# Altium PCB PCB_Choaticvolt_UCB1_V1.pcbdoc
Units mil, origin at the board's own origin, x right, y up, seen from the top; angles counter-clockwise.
Board outline 5539.37 x 2906.58 mil, 2 copper layers (Top Layer, Bottom Layer); 21 components, 11 nets, 90 pads, 17 vias.
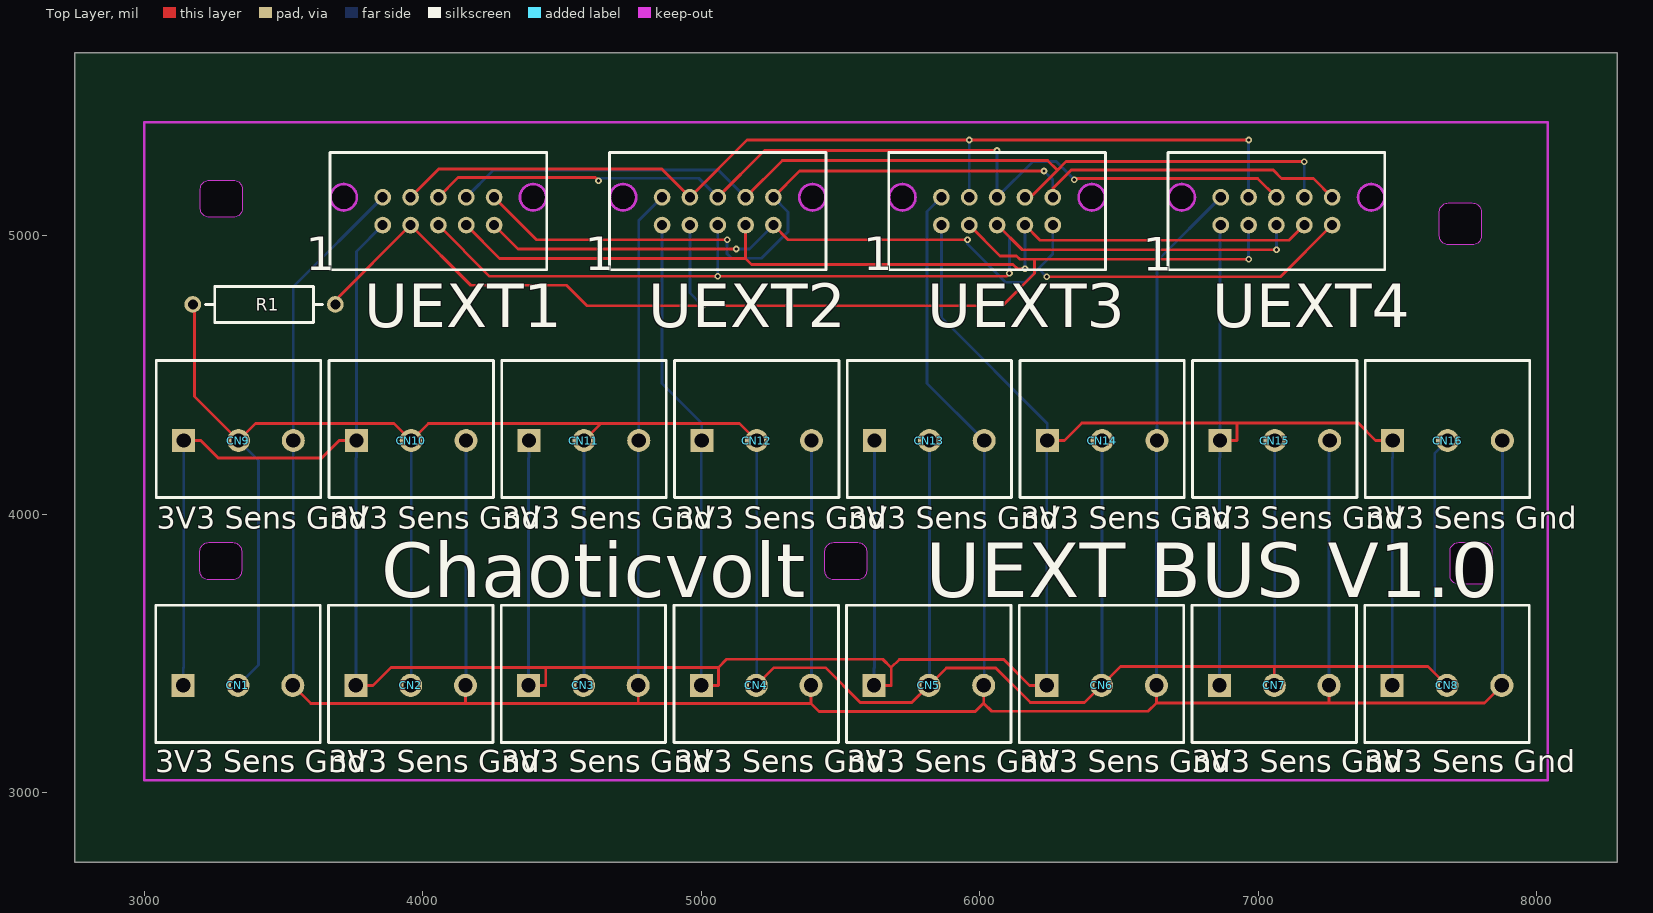
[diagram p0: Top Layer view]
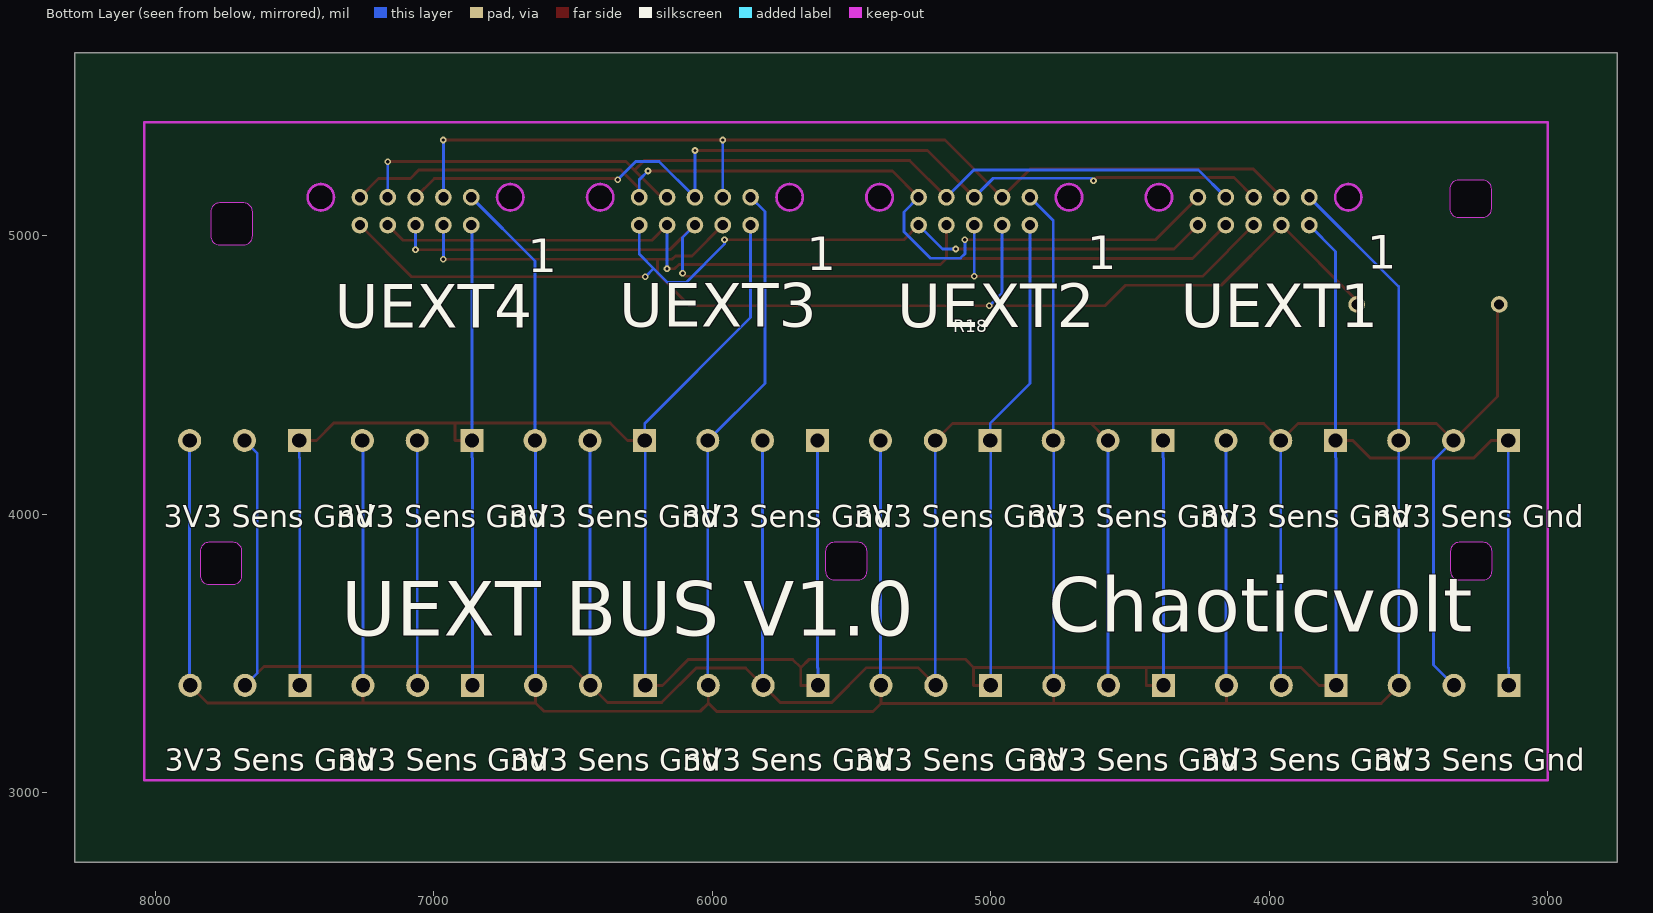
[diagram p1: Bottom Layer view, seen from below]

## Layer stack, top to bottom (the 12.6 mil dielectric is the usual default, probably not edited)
Top Layer: signal copper (thickness not stored)
Dielectric: dielectric 12.6, FR-4, Dk 4.8
Bottom Layer: signal copper (thickness not stored)

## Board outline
8289.37,2750 2750,2750 2750,5656.58 8289.37,5656.58
cut-out: 7682.22,5116.99 7769.23,5116.99 cw(c7769.23,5085.49) 7800.72,5085.49 7800.72,4998.49 cw(c7769.23,4998.49) 7769.23,4966.99 7682.22,4966.99 cw(c7682.22,4998.49) 7650.72,4998.49 7650.72,5085.49 cw(c7682.22,5085.49)
cut-out: 3233.09,5198.99 3319.7,5198.99 cw(c3319.7,5167.49) 3351.2,5167.49 3351.2,5096.63 cw(c3319.7,5096.63) 3319.7,5065.13 3233.09,5065.13 cw(c3233.09,5096.63) 3201.59,5096.63 3201.59,5167.49 cw(c3233.09,5167.49)
cut-out: 3231.09,3897.88 3317.7,3897.88 cw(c3317.7,3866.38) 3349.2,3866.38 3349.2,3795.52 cw(c3317.7,3795.52) 3317.7,3764.02 3231.09,3764.02 cw(c3231.09,3795.52) 3199.59,3795.52 3199.59,3866.38 cw(c3231.09,3866.38)
cut-out: 7720.22,3897.88 7807.23,3897.88 cw(c7807.23,3866.38) 7838.72,3866.38 7838.72,3779.38 cw(c7807.23,3779.38) 7807.23,3747.88 7720.22,3747.88 cw(c7720.22,3779.38) 7688.72,3779.38 7688.72,3866.38 cw(c7720.22,3866.38)
cut-out: 5475.52,3897.88 5562.13,3897.88 cw(c5562.13,3866.38) 5593.63,3866.38 5593.63,3795.52 cw(c5562.13,3795.52) 5562.13,3764.02 5475.52,3764.02 cw(c5475.52,3795.52) 5444.02,3795.52 5444.02,3866.38 cw(c5475.52,3866.38)

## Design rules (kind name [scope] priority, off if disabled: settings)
Clearance copperThickness1oz [All] p1: gap=7 ignorepadtopadclearanceinfootprint=FALSE except(4: Track-Track; 6: Track-SMDPad SMDPad-SMDPad Track-THPad SMDPad-THPad THPad-THPad Track-Via SMDPad-Via THPad-Via Via-Via SMDPad-Fill THPad-Fill Via-Fill Fill-Fill Track-Region SMDPad-Region THPad-Region Via-Region Region-Region Track-Poly SMDPad-Poly THPad-Poly Via-Poly Fill-Poly Region-Poly Poly-Poly Track-Text SMDPad-Text THPad-Text Via-Text Fill-Text Region-Text Poly-Text Text-Text; 6.9: Track-Hole SMDPad-Hole THPad-Hole Via-Hole Fill-Hole Region-Hole Poly-Hole Text-Hole Sheet-Hole; 11.8: Track-Fill Fill-Region Track-Sheet SMDPad-Sheet THPad-Sheet Via-Sheet Fill-Sheet Region-Sheet Poly-Sheet Text-Sheet)
Clearance copperThickness2oz [All] p1: gap=7 ignorepadtopadclearanceinfootprint=FALSE except(6: Track-SMDPad SMDPad-SMDPad Track-THPad SMDPad-THPad THPad-THPad Track-Via SMDPad-Via THPad-Via Via-Via SMDPad-Fill THPad-Fill Via-Fill Fill-Fill Track-Region SMDPad-Region THPad-Region Via-Region Region-Region Track-Poly SMDPad-Poly THPad-Poly Via-Poly Fill-Poly Region-Poly Poly-Poly Track-Text SMDPad-Text THPad-Text Via-Text Fill-Text Region-Text Poly-Text Text-Text; 6.9: Track-Hole SMDPad-Hole THPad-Hole Via-Hole Fill-Hole Region-Hole Poly-Hole Text-Hole Sheet-Hole; 8: Track-Track; 11.8: Track-Fill Fill-Region Track-Sheet SMDPad-Sheet THPad-Sheet Via-Sheet Fill-Sheet Region-Sheet Poly-Sheet Text-Sheet)
DiffPairsRouting differentialPair [All] p1: maxuncoupledlength=10 maxlimit=6 mostfreqgap=6 toplayer_minwidth=5 toplayer_prefwidth=10 toplayer_maxwidth=100 bottomlayer_minwidth=5 bottomlayer_prefwidth=10 bottomlayer_maxwidth=100
PasteMaskExpansion pasteMaskExpansion [All] p1:
PlaneConnect innerPlane [All] p1: planeconnectstyle=Relief reliefexpansion=20 reliefentries=4 reliefconductorwidth=10 reliefairgap=10
PolygonConnect copperRegion [All] p1: connectstyle=Relief reliefentries=4 reliefconductorwidth=10 polygonreliefangle="90 Angle" airgapwidth=10
RoutingVias viaSize [All] p1: viastyle="Through Hole" holewidth=12.0078 minholewidth=11.811 maxholewidth=248.0314 width=24.0158 minwidth=19.685 maxwidth=393.7008
SolderMaskExpansion solderMaskExpansion [All] p1: useseparateexpansions=TRUE expansion=2 expansionbottom=2
Width copperThickness1oz [All] p1: maxlimit=100 minlimit=5 preferedwidth=10
Width copperThickness2oz [All] p1: maxlimit=100 minlimit=8 preferedwidth=10

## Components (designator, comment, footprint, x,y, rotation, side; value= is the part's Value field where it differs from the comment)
CN1 "974-T-DS/03" CONN-TH_3P-P5.00_WECO_974-T-DS-03 3336.28,3384.71 r0 top
CN2 "974-T-DS/03" CONN-TH_3P-P5.00_WECO_974-T-DS-03 3956.51,3384.71 r0 top
CN3 "974-T-DS/03" CONN-TH_3P-P5.00_WECO_974-T-DS-03 4576.75,3384.71 r0 top
CN4 "974-T-DS/03" CONN-TH_3P-P5.00_WECO_974-T-DS-03 5196.98,3384.71 r0 top
CN5 "974-T-DS/03" CONN-TH_3P-P5.00_WECO_974-T-DS-03 5817.22,3384.71 r0 top
CN6 "974-T-DS/03" CONN-TH_3P-P5.00_WECO_974-T-DS-03 6437.45,3384.71 r0 top
CN7 "974-T-DS/03" CONN-TH_3P-P5.00_WECO_974-T-DS-03 7057.69,3384.71 r0 top
CN8 "974-T-DS/03" CONN-TH_3P-P5.00_WECO_974-T-DS-03 7677.93,3384.71 r0 top
CN9 "974-T-DS/03" CONN-TH_3P-P5.00_WECO_974-T-DS-03 3338.16,4264.02 r0 top
CN10 "974-T-DS/03" CONN-TH_3P-P5.00_WECO_974-T-DS-03 3958.4,4264.02 r0 top
CN11 "974-T-DS/03" CONN-TH_3P-P5.00_WECO_974-T-DS-03 4578.64,4264.02 r0 top
CN12 "974-T-DS/03" CONN-TH_3P-P5.00_WECO_974-T-DS-03 5198.87,4264.02 r0 top
CN13 "974-T-DS/03" CONN-TH_3P-P5.00_WECO_974-T-DS-03 5819.11,4264.02 r0 top
CN14 "974-T-DS/03" CONN-TH_3P-P5.00_WECO_974-T-DS-03 6439.34,4264.02 r0 top
CN15 "974-T-DS/03" CONN-TH_3P-P5.00_WECO_974-T-DS-03 7059.58,4264.02 r0 top
CN16 "974-T-DS/03" CONN-TH_3P-P5.00_WECO_974-T-DS-03 7679.81,4264.02 r0 top
R1 "MFR1WSJT-52-2K7" RES-TH_BD3.3-L9.0-P13.00-D0.6 3430,4752.58 r0 top
UEXT1 "15477610" IDC-TH_15477610 4056,5087.58 r0 top
UEXT2 "15477610" IDC-TH_15477610 5059.12,5087.58 r0 top
UEXT3 "15477610" IDC-TH_15477610 6062.24,5087.58 r0 top
UEXT4 "15477610" IDC-TH_15477610 7065.36,5087.58 r0 top

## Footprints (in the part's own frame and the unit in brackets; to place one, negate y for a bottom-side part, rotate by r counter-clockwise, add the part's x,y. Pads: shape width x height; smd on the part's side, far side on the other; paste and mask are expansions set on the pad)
CONN-TH_3P-P5.00_WECO_974-T-DS-03 [mm]
  rect 2.1x2.1 hole 1.3: 1(-5,0)
  round 2.1 hole 1.3: 2(0,0) 3(5,0)
  silkscreen extent -7.5,-5.2 7.5,7.3
IDC-TH_15477610 [mil]
  round 60 hole 36: 1(-200,-50) 2(-200,50) 3(-100,-50) 4(-100,50) 5(0,-50) 6(0,50) 7(100,-50) 8(100,50) 9(200,-50) 10(200,50)
  Multi-Layer board cut-out: -292.92,50 -299.39,73.44 -316.66,90.55 -340.16,96.81 -363.65,90.55 -380.93,73.44 -387.4,50 -387.4,50 -380.93,26.56 -363.65,9.45 -340.16,3.19 -316.66,9.45 -299.39,26.56 -292.92,50
  Multi-Layer board cut-out: 387.4,50 380.93,73.44 363.66,90.55 340.16,96.81 316.67,90.55 299.39,73.44 292.92,50 292.92,50 299.39,26.56 316.67,9.45 340.16,3.19 363.66,9.45 380.93,26.56 387.4,50
  Multi-Layer keep-out circle w10: c-340.16,50 r47.24
  Multi-Layer keep-out circle w10: c340.16,50 r47.24
  silkscreen extent -389,-211 389,211
RES-TH_BD3.3-L9.0-P13.00-D0.6 [mil]
  round 60 hole 36: 1(-255.9,0) 2(255.91,0)
  silkscreen extent -210,-65 210,65

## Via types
v1: diameter 24, hole 12, Top Layer to Bottom Layer, 17 vias

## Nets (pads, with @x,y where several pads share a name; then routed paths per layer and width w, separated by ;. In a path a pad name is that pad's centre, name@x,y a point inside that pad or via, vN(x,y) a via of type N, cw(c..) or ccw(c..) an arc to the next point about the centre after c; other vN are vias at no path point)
$1N825: CN1.2 CN2.2 CN3.2 CN4.2 CN5.2 CN6.2 CN7.2 CN8.2 CN9.2 CN10.2 CN11.2 CN12.2 CN13.2 CN14.2 CN15.2 CN16.2 R1.1 | length 12554.5
  Top Layer w10: R1.1 3180,4746.68 3180,4422.19 CN9.2 ; CN9.2 3399.7,4325.48 3896.9,4325.48 CN10.2 4019.9,4325.48 4640.1,4325.48 ; CN11.2 4640.1,4325.48 ; CN4.2 5260.6,3448.28 5445.7,3448.28 5570.8,3323.18 5755.7,3323.18 CN5.2 5880,3447.48 6057.5,3447.48 6181.7,3323.18 6376,3323.18 CN6.2 6505.4,3452.58 7057.7,3452.58 ; CN12.2 5137.4,4325.48 4640.1,4325.48 ; CN7.2 7057.7,3452.58 ; CN8.2 7610,3452.58 7057.7,3452.58
  Bottom Layer w10: CN1.2 3409.9,3458.28 3409.9,4192.28 CN9.2 ; CN2.2 3958.4,3386.58 CN10.2 ; CN3.2 4578.6,3386.58 CN11.2 ; CN4.2 5198.9,3386.58 CN12.2 ; CN5.2 5819.1,3386.58 CN13.2 ; CN6.2 6439.3,3386.48 CN14.2 ; CN7.2 7059.6,3386.58 CN15.2 ; CN8.2 7633.6,3428.98 7633.6,4217.78 CN16.2
$1N1392: UEXT1.9 UEXT2.9 UEXT3.9 UEXT4.9 | length 3461.6
  Top Layer w10: UEXT1.9 4341.9,4951.68 v1(5125.7,4951.68) ; UEXT2.9 5311.9,4984.78 v1(5956,4984.78) ; v1(6240.2,4852.18) 7080,4852.18 UEXT4.9
  Bottom Layer w10: v1(5125.7,4951.68) 5173.2,4951.68 UEXT2.9 ; v1(5956,4984.78) 5956,4969.28 6093.2,4832.08 6160.7,4832.08 6210.5,4881.88 ; v1(6240.2,4852.18) 6210.5,4881.88 ; UEXT3.9 6262.2,4933.58 6210.5,4881.88
$1N1399: UEXT1.7 UEXT2.7 UEXT3.7 UEXT4.7 | length 3396.3
  Top Layer w10: UEXT1.7 4275.6,4917.98 5159.1,4917.98 ; UEXT2.7 5159.1,4917.98 ; v1(6162.2,4880.58) 6135.7,4880.58 6119.8,4896.38 5180.6,4896.38 5159.1,4917.98 ; UEXT3.7 6216.8,4982.98 7110.8,4982.98 UEXT4.7
  Bottom Layer w10: v1(6162.2,4880.58) UEXT3.7
$1N1421: UEXT1.5 UEXT2.5 UEXT3.5 UEXT4.5 | length 3635.7
  Top Layer w10: UEXT1.5 4240.1,4853.48 v1(5059.1,4853.48) 6095.8,4853.48 v1(6106.5,4864.28) ; UEXT3.5 6064,5037.58 6152.7,4948.88 v1(7065.4,4948.88)
  Bottom Layer w10: v1(5059.1,4853.48) UEXT2.5 ; UEXT3.5 6106.5,4993.28 v1(6106.5,4864.28) ; v1(7065.4,4948.88) UEXT4.5
$1N1566: 
$1N1663: UEXT1.10 UEXT2.10 UEXT3.10 UEXT4.10 | length 3581.3
  Top Layer w10: UEXT1.10 4409,4984.68 v1(5092.8,4984.68) ; UEXT2.10 5353.3,5231.78 v1(6230.9,5231.78) ; UEXT3.10 6262.2,5169.08 6328.4,5235.28 7053.9,5235.28 7084.1,5205.08 7197.9,5205.08 UEXT4.10
  Bottom Layer w10: v1(5092.8,4984.68) 5092.8,4934.58 5108.6,4918.78 5217,4918.78 5311.7,5013.48 5311.7,5084.98 UEXT2.10 ; v1(6230.9,5231.78) 6262.2,5200.48 UEXT3.10
$1N1691: UEXT1.6 UEXT2.6 UEXT3.6 UEXT4.6 | length 3422
  Top Layer w10: UEXT1.6 4126.9,5208.48 4619.6,5208.48 v1(4630.8,5197.28) ; UEXT2.6 5226.7,5305.18 v1(6062.2,5305.18) ; v1(6339.5,5200.88) 6343.7,5205.08 6997.9,5205.08 UEXT4.6
  Bottom Layer w10: v1(4630.8,5197.28) 4639.2,5205.68 4991.1,5205.68 UEXT2.6 ; v1(6062.2,5305.18) UEXT3.6 6190.6,5265.98 6274.5,5265.98 v1(6339.5,5200.88)
$1N1700: UEXT1.4 UEXT2.4 UEXT3.4 UEXT4.4 | length 3588.8
  Top Layer w10: UEXT1.4 4057.1,5238.68 4858,5238.68 UEXT2.4 5164.4,5342.88 v1(5962.2,5342.88) v1(6965.4,5342.88)
  Bottom Layer w10: UEXT3.4 v1(5962.2,5342.88) ; UEXT4.4 v1(6965.4,5342.88)
$1N1774: UEXT1.8 UEXT2.8 UEXT3.8 UEXT4.8 | length 3457.6
  Top Layer w10: UEXT2.8 5291,5269.48 6243.9,5269.48 6279,5234.38 ; UEXT3.8 6182.2,5137.58 6279,5234.38 ; v1(7165.4,5265.48) 6310.1,5265.48 6279,5234.38
  Bottom Layer w10: UEXT1.8 4254.2,5235.78 5060.9,5235.78 UEXT2.8 ; UEXT4.8 v1(7165.4,5265.48)
GND: CN1.3 CN2.3 CN3.3 CN4.3 CN5.3 CN6.3 CN7.3 CN8.3 CN9.3 CN10.3 CN11.3 CN12.3 CN13.3 CN14.3 CN15.3 CN16.3 UEXT1.2 UEXT2.2 UEXT3.2 UEXT4.2 | length 15731.5
  Top Layer w10: CN1.3 3597.9,3319.98 4153.4,3319.98 ; CN2.3 4153.4,3319.98 ; CN3.3 4773.6,3319.98 ; CN4.3 5393.8,3319.98 ; CN5.3 6014.1,3320.68 ; CN6.3 6634.3,3321.78 ; CN7.3 7254.5,3321.78 ; CN8.3 7811.9,3321.78 7254.5,3321.78 ; 4153.4,3319.98 4773.6,3319.98 ; 4773.6,3319.98 5393.8,3319.98 ; 5393.8,3319.98 5423.2,3290.48 5983.9,3290.48 6014.1,3320.68 ; 6014.1,3320.68 6043.2,3291.58 6604.1,3291.58 6634.3,3321.78 ; 6634.3,3321.78 7254.5,3321.78
  Bottom Layer w10: CN1.3 3535,3386.58 CN9.3 3535,4816.58 UEXT1.2 ; CN2.3 4155.2,3386.48 CN10.3 ; CN3.3 4773.6,4262.08 CN11.3 4775.5,5053.98 UEXT2.2 ; CN4.3 5395.7,3386.58 CN12.3 ; UEXT3.2 5810.9,5086.28 5810.9,4469.08 CN13.3 6016,3386.58 CN5.3 ; CN6.3 6634.3,4262.08 CN14.3 6636.2,4908.38 UEXT4.2 ; CN7.3 7254.5,4262.08 CN15.3 ; CN8.3 7876.7,3386.58 CN16.3
VCC: CN1.1 CN2.1 CN3.1 CN4.1 CN5.1 CN6.1 CN7.1 CN8.1 CN9.1 CN10.1 CN11.1 CN12.1 CN13.1 CN14.1 CN15.1 CN16.1 UEXT1.1 UEXT2.1 UEXT3.1 UEXT4.1 | length 15502
  Top Layer w10: CN9.1 3202.8,4263.98 3265.5,4201.28 3637.3,4201.28 3700,4263.98 CN10.1 ; CN2.1 3821.2,3384.68 3885.6,3449.18 4441.4,3449.18 ; CN3.1 4441.4,3384.68 4441.4,3449.18 ; CN4.1 5061.6,3384.68 5061.6,3449.18 ; CN5.1 5681.9,3384.68 5681.9,3448.28 ; CN6.1 6179.1,3384.68 6086.2,3477.68 5711.2,3477.68 5681.9,3448.28 ; CN14.1 6304,4263.98 6366.5,4326.48 6924.2,4326.48 ; CN15.1 6924.2,4263.98 6924.2,4326.48 ; CN16.1 7421.5,4263.98 7359.1,4326.48 6924.2,4326.48 ; 4441.4,3449.18 5061.6,3449.18 ; 5061.6,3449.18 5090.9,3478.48 5651.7,3478.48 5681.9,3448.28
  Bottom Layer w10: CN1.1 3139.4,3446.18 3141.3,3448.08 CN9.1 ; CN2.1 3759.7,4200.68 3761.5,4202.48 CN10.1 3761.5,4943.08 UEXT1.1 ; CN3.1 4379.9,4200.58 4381.8,4202.48 CN11.1 ; UEXT2.1 4859.1,4468.38 5002,4325.48 CN12.1@5002,4294.68 ; CN4.1 5000.1,4292.78 CN12.1@5002,4294.68 ; CN12.1 CN12.1@5002,4294.68 ; CN5.1 5620.4,3446.18 5622.3,3448.08 CN13.1 ; UEXT3.1 5862.2,4705.78 6242.5,4325.48 CN14.1@6242.5,4294.68 ; CN6.1 6240.6,4292.78 CN14.1@6242.5,4294.68 ; CN14.1 CN14.1@6242.5,4294.68 ; CN7.1 6860.8,4200.58 6862.7,4202.48 CN15.1 6862.7,5034.88 UEXT4.1 ; CN8.1 7481.1,4200.58 7483,4202.48 CN16.1
pads on no net: R1.2 UEXT1.3 UEXT2.3 UEXT3.3 UEXT4.3
copper on no net: | length 4342.7
  Top Layer w10: 3685.91,4752.58 3685.91,4767.49 3956,5037.58 4172.1,4821.48 4516.5,4821.48 4590.4,4747.58 v1(5005.2,4747.58) 6080.8,4747.58 6196.6,4863.38 6196.6,4915.28 ; 5962.2,5037.58 6073.2,4926.58 6132.3,4926.58 6143.7,4915.28 6196.6,4915.28 ; v1(6965.4,4915.28) 6196.6,4915.28
  Bottom Layer w10: 4959.1,5037.58 4959.1,4793.68 v1(5005.2,4747.58) ; v1(6965.4,4915.28) 6965.4,5037.58

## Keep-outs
Board Outline Layer:
  lines w10: 3000,3044.38 8039.37,3044.38 8039.37,5406.58 3000,5406.58 3000,3044.38
Multi-Layer:
  region: 7682.22,5116.99 7769.23,5116.99 cw(c7769.23,5085.49) 7800.72,5085.49 7800.72,4998.49 cw(c7769.23,4998.49) 7769.23,4966.99 7682.22,4966.99 cw(c7682.22,4998.49) 7650.72,4998.49 7650.72,5085.49 cw(c7682.22,5085.49)
  region: 3233.09,5198.99 3319.7,5198.99 cw(c3319.7,5167.49) 3351.2,5167.49 3351.2,5096.63 cw(c3319.7,5096.63) 3319.7,5065.13 3233.09,5065.13 cw(c3233.09,5096.63) 3201.59,5096.63 3201.59,5167.49 cw(c3233.09,5167.49)
  region: 3231.09,3897.88 3317.7,3897.88 cw(c3317.7,3866.38) 3349.2,3866.38 3349.2,3795.52 cw(c3317.7,3795.52) 3317.7,3764.02 3231.09,3764.02 cw(c3231.09,3795.52) 3199.59,3795.52 3199.59,3866.38 cw(c3231.09,3866.38)
  region: 7720.22,3897.88 7807.23,3897.88 cw(c7807.23,3866.38) 7838.72,3866.38 7838.72,3779.38 cw(c7807.23,3779.38) 7807.23,3747.88 7720.22,3747.88 cw(c7720.22,3779.38) 7688.72,3779.38 7688.72,3866.38 cw(c7720.22,3866.38)
  region: 5475.52,3897.88 5562.13,3897.88 cw(c5562.13,3866.38) 5593.63,3866.38 5593.63,3795.52 cw(c5562.13,3795.52) 5562.13,3764.02 5475.52,3764.02 cw(c5475.52,3795.52) 5444.02,3795.52 5444.02,3866.38 cw(c5475.52,3866.38)

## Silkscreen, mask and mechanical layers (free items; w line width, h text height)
Top Silkscreen Layer:
  text "1" at 4581.45,4875.67 h120
  text "1" at 5581.45,4875.67 h120
  text "1" at 3580,4874.58 h120
  text "1" at 6585.45,4873.67 h120
  text "3V3 Sens Gnd" at 3044,3946.74 h78.74
  text "3V3 Sens Gnd" at 3666,3946.74 h78.74
  text "3V3 Sens Gnd" at 4283.56,3946.74 h78.74
  text "3V3 Sens Gnd" at 4907.56,3946.74 h78.74
  text "3V3 Sens Gnd" at 5525.56,3946.74 h78.74
  text "3V3 Sens Gnd" at 6147.56,3946.74 h78.74
  text "3V3 Sens Gnd" at 6765.56,3946.74 h78.74
  text "3V3 Sens Gnd" at 7385.56,3946.74 h78.74
  text "Chaoticvolt" at 3850.44,3700.98 h196.85
  text "UEXT BUS V1.0" at 5806.01,3700.98 h196.85
  text "3V3 Sens Gnd" at 3040,3072.74 h78.74
  text "3V3 Sens Gnd" at 3662,3072.74 h78.74
  text "3V3 Sens Gnd" at 4279.56,3072.74 h78.74
  text "3V3 Sens Gnd" at 4903.56,3072.74 h78.74
  text "3V3 Sens Gnd" at 5521.56,3072.74 h78.74
  text "3V3 Sens Gnd" at 6143.56,3072.74 h78.74
  text "3V3 Sens Gnd" at 6761.56,3072.74 h78.74
  text "3V3 Sens Gnd" at 7381.56,3072.74 h78.74
Bottom Silkscreen Layer:
  text "1" at 3648,4880.58 h120
  text "1" at 4654,4878.58 h120
  text "1" at 5660,4874.58 h120
  text "1" at 6662,4868.58 h120
  text "UEXT3" at 6334,4672.58 h157.48
  text "UEXT1" at 4318,4670.58 h157.48
  text "UEXT2" at 5336,4670.58 h157.48
  text "UEXT4" at 7356,4668.58 h157.48
  text "R18" at 5135,4653.58 h45
  text "3V3 Sens Gnd" at 3628,3952.74 h78.74
  text "3V3 Sens Gnd" at 4250,3952.74 h78.74
  text "3V3 Sens Gnd" at 4867.56,3952.74 h78.74
  text "3V3 Sens Gnd" at 5491.56,3952.74 h78.74
  text "3V3 Sens Gnd" at 6109.56,3952.74 h78.74
  text "3V3 Sens Gnd" at 6731.56,3952.74 h78.74
  text "3V3 Sens Gnd" at 7349.56,3952.74 h78.74
  text "3V3 Sens Gnd" at 7969.56,3952.74 h78.74
  text "Chaoticvolt" at 4794,3576.58 h196.85
  text "UEXT BUS V1.0" at 7332,3562.58 h196.85
  text "3V3 Sens Gnd" at 3624,3078.74 h78.74
  text "3V3 Sens Gnd" at 4246,3078.74 h78.74
  text "3V3 Sens Gnd" at 4863.56,3078.74 h78.74
  text "3V3 Sens Gnd" at 5487.56,3078.74 h78.74
  text "3V3 Sens Gnd" at 6105.56,3078.74 h78.74
  text "3V3 Sens Gnd" at 6727.56,3078.74 h78.74
  text "3V3 Sens Gnd" at 7345.56,3078.74 h78.74
  text "3V3 Sens Gnd" at 7965.56,3078.74 h78.74
Mechanical Layer:
  lines w1: 3199.59,3795.52 ccw(c3231.09,3795.52) 3231.09,3764.02 3317.7,3764.02 ccw(c3317.7,3795.52) 3349.2,3795.52 3349.2,3866.38 ccw(c3317.7,3866.38) 3317.7,3897.88 3231.09,3897.88 ccw(c3231.09,3866.38) 3199.59,3866.38 3199.59,3795.52 ; 3201.59,5096.63 ccw(c3233.09,5096.63) 3233.09,5065.13 3319.7,5065.13 ccw(c3319.7,5096.63) 3351.2,5096.63 3351.2,5167.49 ccw(c3319.7,5167.49) 3319.7,5198.99 3233.09,5198.99 ccw(c3233.09,5167.49) 3201.59,5167.49 3201.59,5096.63 ; 5444.02,3795.52 ccw(c5475.52,3795.52) 5475.52,3764.02 5562.13,3764.02 ccw(c5562.13,3795.52) 5593.63,3795.52 5593.63,3866.38 ccw(c5562.13,3866.38) 5562.13,3897.88 5475.52,3897.88 ccw(c5475.52,3866.38) 5444.02,3866.38 5444.02,3795.52 ; 7650.72,4998.49 ccw(c7682.22,4998.49) 7682.22,4966.99 7769.23,4966.99 ccw(c7769.23,4998.49) 7800.72,4998.49 7800.72,5085.49 ccw(c7769.23,5085.49) 7769.23,5116.99 7682.22,5116.99 ccw(c7682.22,5085.49) 7650.72,5085.49 7650.72,4998.49 ; 7688.72,3779.38 ccw(c7720.22,3779.38) 7720.22,3747.88 7807.23,3747.88 ccw(c7807.23,3779.38) 7838.72,3779.38 7838.72,3866.38 ccw(c7807.23,3866.38) 7807.23,3897.88 7720.22,3897.88 ccw(c7720.22,3866.38) 7688.72,3866.38 7688.72,3779.38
